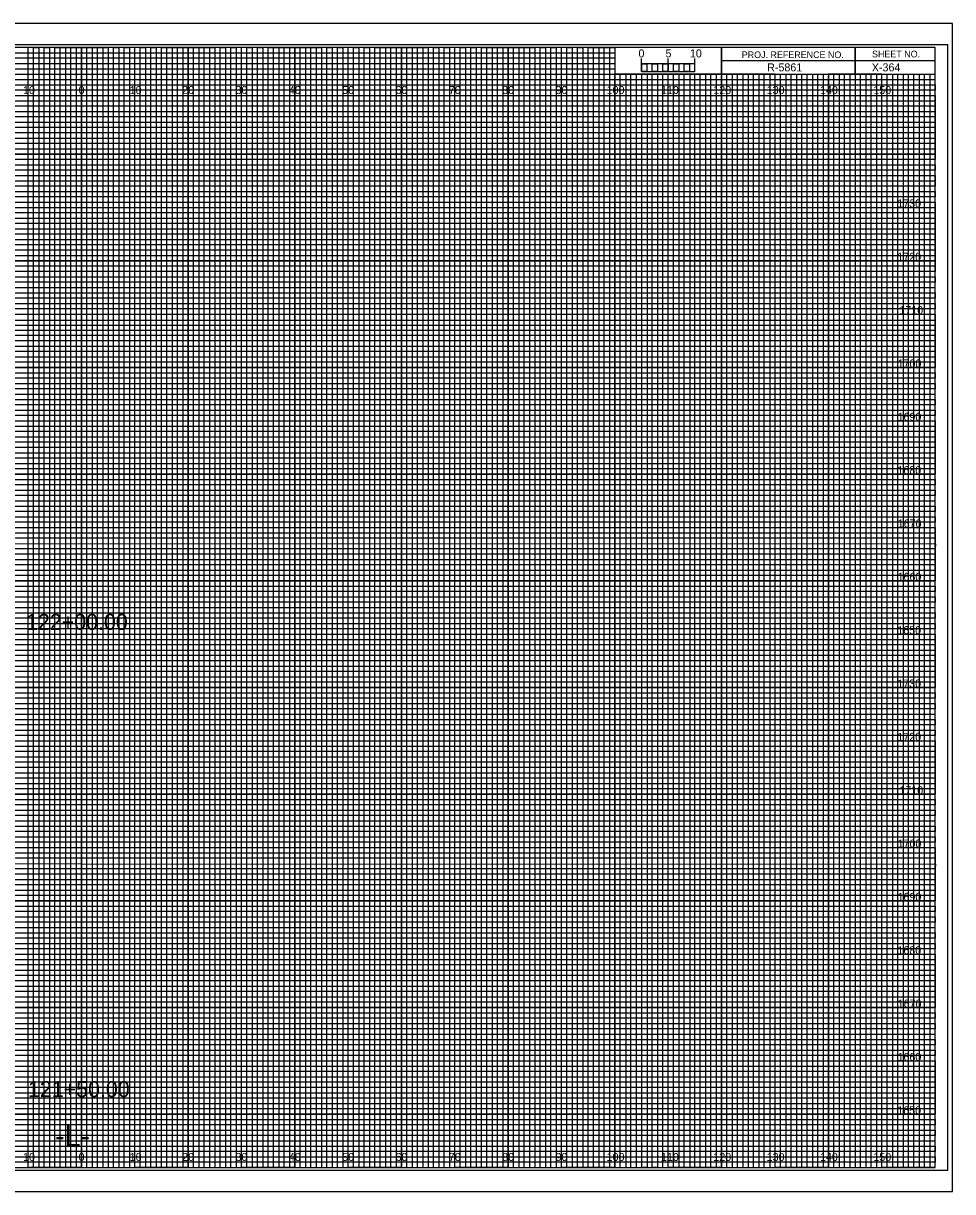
# Model space of a CAD drawing. Extents: x -13 to 323, y -5 to 2414.
# Drawn here: x 149.1 to 323.3, y -4.5 to 214.5 of the extents above; entities that cross this region are included whole.
import ezdxf

# ---------------------------------------------------------------- set-up
doc = ezdxf.new("R2010")
doc.units = 0
for name, color, linetype in [('Prop XS Alignment Label', 7, 'Continuous'), ('Prop XS Bar Scale Labels', 7, 'Continuous'), ('Prop XS Elevation Labels', 7, 'Continuous'), ('Prop XS Offset Labels', 7, 'Continuous'), ('Prop XS Project Number', 7, 'Continuous'), ('Prop XS Sheet Number', 7, 'Continuous'), ('Prop XS Station Labels', 7, 'Continuous'), ('Sheet Cross Section CELL', 7, 'Continuous'), ('Sheet Cross Section Grid Major CELL', 7, 'Continuous'), ('Sheet Cross Section Grid Middle CELL', 7, 'Continuous'), ('Sheet Cross Section Grid Minor 1 CELL', 7, 'Continuous'), ('Sheet Cross Section Grid Minor 2 CELL', 7, 'Continuous'), ('Sheet Cross Section Scale CELL', 7, 'Continuous'), ('Sheet Cutting Line CELL', 7, 'Continuous'), ('Sheet DOT Grid CELL', 7, 'Continuous'), ('Sheet Plot Border Inside CELL', 7, 'Continuous'), ('Sheet Plot Border Outside CELL', 7, 'Continuous')]:
    doc.layers.add(name, color=color, linetype=linetype)

msp = doc.modelspace()

# ---------------------------------------------------------------- linework, layer by layer
at = {"layer": 'Sheet Cross Section CELL'}
for p, q in [((305, 210), (305, 205)), ((305, 205), (305, 210)), ((280, 207.5), (280, 205)), ((320, 207.49), (280, 207.49)), ((280, 205), (320, 205))]:
    msp.add_line(p, q, dxfattribs=at)
for points in [[(320, 210), (0, 210), (0, 0), (320, 0)], [(280, 210), (260, 210), (260, 205.03), (280, 205.03)], [(320, 210), (280, 210), (280, 205), (320, 205)]]:
    msp.add_lwpolyline(points, close=True, dxfattribs=at)
at = {"layer": 'Sheet Cross Section Grid Major CELL'}
for p, q in [((150, 210), (140, 210)), ((150, 0), (150, 210)), ((170, 210), (160, 210)), ((160, 210), (160, 0)), ((170, 0), (170, 210)), ((190, 210), (180, 210)), ((180, 210), (180, 0)), ((190, 0), (190, 210)), ((210, 210), (200, 210)), ((200, 210), (200, 0)), ((210, 0), (210, 210)), ((230, 210), (220, 210)), ((220, 210), (220, 0)), ((230, 0), (230, 210)), ((250, 210), (240, 210)), ((240, 210), (240, 0)), ((250, 0), (250, 210)), ((260, 210), (260, 0)), ((270, 0), (270, 205)), ((290, 205), (280, 205)), ((280, 205), (280, 0)), ((290, 0), (290, 205)), ((310, 205), (300, 205)), ((300, 205), (300, 0)), ((310, 0), (310, 205)), ((160, 0), (150, 0)), ((180, 0), (170, 0)), ((200, 0), (190, 0)), ((220, 0), (210, 0)), ((240, 0), (230, 0)), ((260, 0), (250, 0)), ((280, 0), (270, 0)), ((300, 0), (290, 0)), ((320, 0), (310, 0)), ((320, 0), (320, 0))]:
    msp.add_line(p, q, dxfattribs=at)
for points in [[(0, 200), (320, 200), (320, 190), (0, 190)], [(0, 180), (320, 180), (320, 170), (0, 170)], [(0, 160), (320, 160), (320, 150), (0, 150)], [(0, 140), (320, 140), (320, 130), (0, 130)], [(0, 120), (320, 120), (320, 110), (0, 110)], [(0, 100), (320, 100), (320, 90), (0, 90)], [(0, 80), (320, 80), (320, 70), (0, 70)], [(0, 60), (320, 60), (320, 50), (0, 50)], [(0, 40), (320, 40), (320, 30), (0, 30)], [(0, 20), (320, 20), (320, 10), (0, 10)]]:
    msp.add_lwpolyline(points, dxfattribs=at)
at = {"layer": 'Sheet Cross Section Grid Middle CELL'}
for points in [[(145, 0), (155, 0), (155, 210), (165, 210), (165, 0), (175, 0), (175, 210), (185, 210), (185, 0), (195, 0), (195, 210), (205, 210), (205, 0), (215, 0), (215, 210), (225, 210), (225, 0), (235, 0), (235, 210), (245, 210), (245, 0), (255, 0), (255, 210), (259.93, 210), (260, 210), (260, 205), (264.99, 205), (264.99, 0), (275, 0), (275, 205), (285, 205), (285, 0), (295, 0), (295, 205), (305, 205), (305, 0), (315, 0), (315, 205)], [(0, 205), (275, 205)], [(0, 185), (320, 185), (320, 195), (0, 195)], [(0, 165), (320, 165), (320, 175), (0, 175)], [(0, 145), (320, 145), (320, 155), (0, 155)], [(0, 125), (320, 125), (320, 135), (0, 135)], [(0, 105), (320, 105), (320, 115), (0, 115)], [(0, 85), (320, 85), (320, 95), (0, 95)], [(0, 65), (320, 65), (320, 75), (0, 75)], [(0, 45), (320, 45), (320, 55), (0, 55)], [(0, 25), (320, 25), (320, 35), (0, 35)], [(0, 5), (320, 5), (320, 15), (0, 15)]]:
    msp.add_lwpolyline(points, dxfattribs=at)
at = {"layer": 'Sheet Cross Section Grid Minor 1 CELL'}
for p, q in [((0, 209), (260, 209)), ((260, 209), (260, 207.98)), ((260, 207.98), (0, 207.98)), ((0, 207), (260, 207)), ((260, 205.89), (0, 205.89)), ((260, 207), (260, 205.89)), ((0, 204), (320, 204))]:
    msp.add_line(p, q, dxfattribs=at)
for points in [[(0, 203), (270, 203), (320, 203), (320, 202), (0, 202)], [(0, 201), (320, 201), (320, 199), (0, 199)], [(0, 198), (320, 198), (320, 197), (0, 196.98)], [(0, 196), (320, 196), (320, 194), (0, 194)], [(0, 193), (320, 193), (320, 192), (0, 192)], [(0, 191), (320, 191), (320, 189), (0, 189)], [(0, 188), (320, 188), (320, 187), (0, 187)], [(0, 186), (320, 186), (320, 184), (0, 184)], [(0, 183), (320, 183), (320, 182), (0, 182)], [(0, 181), (320, 181), (320, 179), (0, 179)], [(0, 178), (320, 178), (320, 177), (0, 177)], [(0, 176), (320, 176), (320, 173.95), (320, 173), (320, 172), (0, 172)], [(0, 174), (320, 174), (320, 173), (0, 173)], [(0, 171), (320, 171), (320, 169), (0, 169.03)], [(0, 169.03), (320, 169), (320, 168), (0, 168)], [(0, 167), (320, 167), (320, 166), (0, 166)], [(0, 164), (320, 164), (320, 163), (0, 163)], [(0, 162), (320, 162), (320, 161), (0, 161)], [(-0.07, 158.89), (320, 158.89), (320, 157.88), (-0.07, 157.88)], [(0, 157), (320, 157), (320, 156), (0, 156)], [(0, 154), (320, 154), (320, 153), (0, 153)], [(0, 152), (320, 152), (320, 151), (0, 151)], [(0, 149), (320, 149), (320, 148), (0, 148)], [(0, 147), (320, 147), (320, 146), (0, 146)], [(0, 144), (320, 144), (320, 143), (0, 143)], [(0, 142), (320, 142), (320, 141), (0, 141)], [(0, 139), (320, 139), (319.99, 137.98), (0, 138)], [(0, 137), (320, 137), (320, 136), (0, 136)], [(0, 134), (320, 134), (320, 133), (0, 133)], [(0, 132), (320, 132), (320, 131), (0, 131)], [(0, 129), (320, 129), (320, 128), (0, 128)], [(0, 127), (320, 127), (320, 126), (0, 126)], [(0, 124), (320, 124), (320, 123), (0, 123)], [(0, 122), (320, 122), (320, 121), (0, 121)], [(0, 119), (320, 119), (320, 118), (0, 118)], [(0, 116.99), (320.07, 116.91), (320, 116), (0, 116)], [(0, 114), (320, 114), (320, 113), (0, 113)], [(0, 112), (320, 112), (320, 111), (0, 111)], [(0, 109), (320, 109), (320, 108), (0, 108)], [(0, 107), (320, 107), (320, 106), (0, 106)], [(0, 104), (320, 104), (320, 103), (0, 103)], [(0, 102), (320, 102), (320, 101), (0, 101)], [(0, 99), (320, 99), (320, 98), (0, 98)], [(0, 97), (320, 97), (320, 96), (0, 96)], [(0, 94), (320, 94), (320, 93), (0, 93)], [(0, 92), (320, 92), (320, 91), (0, 91)], [(0, 89), (320, 89), (320, 88), (0, 88)], [(0, 87), (320, 87), (320, 86), (0, 86)], [(0, 84), (320, 84), (320, 83), (0, 83)], [(0, 82), (320, 82), (320, 81), (0, 81)], [(0, 79), (320, 79), (319.99, 77.98), (0, 78)], [(0, 77), (320, 77), (320, 76), (0, 76)], [(0, 74), (320, 74), (320, 73), (0, 73)], [(0, 72), (320, 72), (320, 71), (0, 71)], [(0, 69), (320, 69), (320, 68), (0, 68)], [(0, 67), (320, 67), (320, 66), (0, 66)], [(0, 64), (320, 64), (320, 63), (0, 63)], [(0, 62), (320, 62), (320, 61), (0, 61)], [(0, 59), (320, 59), (320, 58), (0, 58)], [(0, 56.99), (320.07, 56.91), (320, 56), (0, 56)], [(0, 54), (320, 54), (320, 53), (0, 53)], [(0, 52), (320, 52), (320, 51), (0, 51)], [(0, 49), (320, 49), (320, 48), (0, 48)], [(0, 47), (320, 47), (320, 46), (0, 46)], [(0, 44), (320, 44), (320, 43), (0, 43)], [(0, 42), (320, 42), (320, 41), (0, 41)], [(0, 39), (320, 39), (320, 38), (0, 38)], [(0, 37), (320, 37), (320, 36), (0, 36)], [(0, 34), (320, 34), (320, 33), (0, 33)], [(0, 32), (320, 32), (320, 31), (0, 31)], [(0, 29), (320, 29), (320, 28), (0, 28)], [(0, 27), (320, 27), (320, 26), (0, 26)], [(0, 24), (320, 24), (320, 23), (0, 23)], [(0, 22), (320, 22), (320, 21), (0, 21)], [(0, 19), (320, 19), (320, 18), (0, 18)], [(0, 17), (320, 17), (320, 16), (0, 16)], [(0, 14), (320, 14), (320, 13), (0, 13)], [(0, 12), (320, 12), (320, 11), (0, 11)], [(0, 9), (320, 9), (320, 8), (0, 8)], [(0, 7), (320, 7), (320, 6), (0, 6)], [(0, 4), (320, 4), (320, 3), (0, 3)], [(0, 2), (320, 2), (320, 1), (0, 1)]]:
    msp.add_lwpolyline(points, dxfattribs=at)
at = {"layer": 'Sheet Cross Section Grid Minor 2 CELL'}
for p, q in [((267, 205), (266.01, 205)), ((266.01, 205), (266.01, 0)), ((267, 0), (267, 205)), ((269, 205), (268, 205)), ((268, 205), (268, 0)), ((269, 0), (269, 205)), ((266.01, 0), (265, 0)), ((268, 0), (267, 0))]:
    msp.add_line(p, q, dxfattribs=at)
for points in [[(150, 0), (151, 0), (151, 210), (152, 210), (152, 0)], [(152, 0), (153, 0), (153, 210), (154, 210), (154, 0)], [(155, 0), (156, 0), (156, 210), (157, 210), (157, 0)], [(157, 0), (158, 0), (158, 210), (159, 210), (159, 0)], [(160, 0), (161, 0), (161, 210), (162, 210), (162, 0)], [(162, 0), (163, 0), (163, 210), (164, 210), (164, 0)], [(165, 0), (166, 0), (166, 210), (167, 210), (167, 0)], [(167, 0), (168, 0), (168, 210), (169, 210), (169, 0)], [(170, 0), (171, 0), (171, 210), (172, 210), (172, 0)], [(172, 0), (173, 0), (173, 210), (174, 210), (174, 0)], [(175, 0), (176, 0), (176, 210), (177, 210), (177, 0)], [(177, 0), (178, 0), (178, 210), (179, 210), (179, 0)], [(180, 0), (181, 0), (181, 210), (182, 210), (182, 0)], [(182, 0), (183, 0), (183, 210), (184, 210), (184, 0)], [(185, 0), (186, 0), (186, 210), (187, 210), (187, 0)], [(187, 0), (188, 0), (188, 210), (189, 210), (189, 0)], [(190, 0), (191, 0), (191, 210), (192, 210), (192, 0)], [(192, 0), (193, 0), (193, 210), (194, 210), (194, 0)], [(195, 0), (196, 0), (196, 210), (197, 210), (197, 0)], [(197, 0), (198, 0), (198, 210), (199, 210), (199, 0)], [(200, 0), (201, 0), (201, 210), (202, 210), (202, 0)], [(202, 0), (203, 0), (203, 210), (204, 210), (204, 0)], [(205, 0), (206, 0), (206, 210), (207, 210), (207, 0)], [(207, 0), (208, 0), (208, 210), (209, 210), (209, 0)], [(210, 0), (211, 0), (211, 210), (212, 210), (212, 0)], [(212, 0), (213, 0), (213, 210), (214, 210), (214, 0)], [(215, 0), (216, 0), (216, 210), (217, 210), (217, 0)], [(217, 0), (218, 0), (218, 210), (219, 210), (219, 0)], [(220, 0), (221, 0), (221, 210), (222, 210), (222, 0)], [(222, 0), (223, 0), (223, 210), (224, 210), (224, 0)], [(225, 0), (226, 0), (226, 210), (227, 210), (227, 0)], [(227, 0), (228, 0), (228, 210), (229, 210), (229, 0)], [(230, 0), (231, 0), (231, 210), (232, 210), (232, 0)], [(232, 0), (233, 0), (233, 210), (234, 210), (234, 0)], [(235, 0), (236, 0), (236, 210), (237, 210), (237, 0)], [(237, 0), (238, 0), (238, 210), (239, 210), (239, 0)], [(240, 0), (241, 0), (241, 210), (242, 210), (242, 0)], [(242, 0), (243, 0), (243, 210), (244, 210), (244, 0)], [(245, 0), (246, 0), (246, 210), (247, 210), (247, 0)], [(247, 0), (248, 0), (248, 210), (249, 210), (249, 0)], [(250, 0), (251, 0), (251, 210), (252, 210), (252, 0)], [(252, 0), (253, 0), (253, 210), (254, 210), (254, 0)], [(255, 0), (256, 0), (256, 210), (257, 210), (257, 0)], [(257, 0), (258, 0), (258, 210), (259, 210), (259, 0)], [(260, 0), (261, 0), (261, 205), (262.02, 205), (262.02, 0)], [(262, 0), (263, 0), (263, 205), (263.99, 205), (263.99, 0)], [(270, 0), (270.98, 0), (270.98, 205), (272, 205), (272, 0)], [(272, 0), (273, 0), (273, 205), (274.05, 205), (274.05, 0)], [(275, 0), (276, 0), (276, 205), (277, 205), (277, 0)], [(277, 0), (278, 0), (278, 205), (279, 205), (279, 0)], [(280, 0), (281, 0), (281, 205), (282, 205), (282, 0)], [(282, 0), (283, 0), (283, 205), (284, 205), (284, 0)], [(285, 0), (286, 0), (286, 205), (287, 205), (287, 0)], [(287, 0), (288, 0), (288, 205), (289, 205), (289, 0)], [(290, 0), (291, 0), (291, 205), (292, 205), (292, 0)], [(292, 0), (293, 0), (293, 205), (294, 205), (294, 0)], [(295, 0), (296, 0), (296, 205), (297, 205), (297, 0)], [(297, 0), (298, 0), (298, 205), (299, 205), (299, 0)], [(300, 0), (301, 0), (301, 205), (302, 205), (302, 0)], [(302, 0), (303, 0), (303, 205), (304, 205), (304, 0)], [(305, 0), (306, 0), (306, 205), (307, 205), (307, 0)], [(307, 0), (308, 0), (308, 205), (309, 205), (309, 0)], [(310, 0), (311, 0), (311, 205), (312, 205), (312, 0)], [(312, 0), (313, 0), (313, 205), (314, 205), (314, 0)], [(315, 0), (316, 0), (316, 205), (317, 205), (317, 0)], [(317, 0), (318, 0), (318, 205), (319, 205), (319, 0)]]:
    msp.add_lwpolyline(points, dxfattribs=at)
at = {"layer": 'Sheet Cross Section Scale CELL'}
for p, q in [((265, 205.49), (265, 207.9)), ((265, 206.9), (265, 207.9)), ((270, 205.49), (270, 207.9)), ((275, 205.49), (275, 207.9)), ((275, 206.9), (275, 207.9))]:
    msp.add_line(p, q, dxfattribs=at)
for points in [[(275, 206.9), (265, 206.9), (265, 205.49), (275, 205.49)], [(265, 206.9), (266, 206.9), (266, 205.49), (265, 205.49)], [(267, 206.9), (268, 206.9), (268, 205.49), (267, 205.49)], [(269, 206.9), (270, 206.9), (270, 205.49), (269, 205.49)], [(271, 206.9), (272, 206.9), (272, 205.49), (271, 205.49)], [(273, 206.9), (274, 206.9), (274, 205.49), (273, 205.49)]]:
    msp.add_lwpolyline(points, close=True, dxfattribs=at)
at = {"layer": 'Sheet Cutting Line CELL'}
for p, q in [((323.3, 214.5), (-13.4, 214.5)), ((-13.4, -4.5), (323.3, -4.5))]:
    msp.add_line(p, q, dxfattribs=at)
at = {"layer": 'Sheet DOT Grid CELL'}
for p, q in [((150, 0), (150, 210)), ((160, 0), (160, 210)), ((170, 0), (170, 210)), ((180, 0), (180, 210)), ((190, 0), (190, 210)), ((200, 0), (200, 210)), ((210, 0), (210, 210)), ((220, 0), (220, 210)), ((230, 0), (230, 210)), ((240, 0), (240, 210)), ((250, 0), (250, 210)), ((260, 0), (260, 204.69)), ((270, 0), (270, 204.69)), ((280, 0), (280, 204.69)), ((290, 0), (290, 204.69)), ((300, 0), (300, 204.69)), ((310, 0), (310, 204.69)), ((0, 200), (320, 200)), ((0, 190), (320, 190)), ((0, 180), (320, 180)), ((0, 170), (320, 170)), ((0, 160), (320, 160)), ((0, 150), (320, 150)), ((0, 140), (320, 140)), ((0, 130), (320, 130)), ((0, 120), (320, 120)), ((0, 110), (320, 110)), ((0, 100), (320, 100)), ((0, 90), (320, 90)), ((0, 80), (320, 80)), ((0, 70), (320, 70)), ((0, 60), (320, 60)), ((0, 50), (320, 50)), ((0, 40), (320, 40)), ((0, 30), (320, 30)), ((0, 20), (320, 20)), ((0, 10), (320, 10))]:
    msp.add_line(p, q, dxfattribs=at)
at = {"layer": 'Sheet Plot Border Inside CELL'}
msp.add_lwpolyline([(-10.8, -0.5), (322.4, -0.5), (322.4, 210.5), (-10.8, 210.5)], close=True, dxfattribs=at)
at = {"layer": 'Sheet Plot Border Outside CELL'}
msp.add_lwpolyline([(-13.4, -4.5), (323.3, -4.5), (323.3, 214.5), (-13.4, 214.5)], close=True, dxfattribs=at)

# ---------------------------------------------------------------- texts
at = {"layer": 'Prop XS Alignment Label'}
msp.add_text('-L-', height=4, dxfattribs=at).set_placement((155.06, 4))
at = {"layer": 'Prop XS Bar Scale Labels'}
for s, p in [('5', (269.47, 208.12)), ('10', (274.04, 208.12))]:
    msp.add_text(s, height=1.5, dxfattribs=at).set_placement(p)
at = {"layer": 'Prop XS Elevation Labels'}
for s, p in [('1730', (312.92, 180)), ('1720', (312.93, 170)), ('1710', (313.31, 160)), ('1700', (312.98, 150)), ('1690', (312.97, 140)), ('1680', (312.95, 130)), ('1670', (313, 120)), ('1660', (312.97, 110)), ('1650', (312.92, 100)), ('1730', (312.92, 90)), ('1720', (312.93, 80)), ('1710', (313.31, 70)), ('1700', (312.98, 60)), ('1690', (312.97, 50)), ('1680', (312.95, 40)), ('1670', (313, 30)), ('1660', (312.97, 20)), ('1650', (312.92, 10))]:
    msp.add_text(s, height=1.5, dxfattribs=at).set_placement(p)
at = {"layer": 'Prop XS Offset Labels'}
for s, p in [('10', (149.04, 201.25)), ('0', (159.45, 201.25)), ('0', (159.45, 201.25)), ('10', (169.04, 201.25)), ('20', (178.86, 201.25)), ('30', (188.86, 201.25)), ('40', (198.86, 201.25)), ('50', (208.86, 201.25)), ('60', (218.86, 201.25)), ('70', (228.86, 201.25)), ('80', (238.86, 201.25)), ('90', (248.86, 201.25)), ('100', (258.44, 201.25)), ('110', (268.62, 201.25)), ('120', (278.44, 201.25)), ('130', (288.44, 201.25)), ('140', (298.44, 201.25)), ('150', (308.44, 201.25)), ('10', (149.04, 1.25)), ('0', (159.45, 1.25)), ('0', (159.45, 1.25)), ('10', (169.04, 1.25)), ('20', (178.86, 1.25)), ('30', (188.86, 1.25)), ('40', (198.86, 1.25)), ('50', (208.86, 1.25)), ('60', (218.86, 1.25)), ('70', (228.86, 1.25)), ('80', (238.86, 1.25)), ('90', (248.86, 1.25)), ('100', (258.44, 1.25)), ('110', (268.62, 1.25)), ('120', (278.44, 1.25)), ('130', (288.44, 1.25)), ('140', (298.44, 1.25)), ('150', (308.44, 1.25))]:
    msp.add_text(s, height=1.5, dxfattribs=at).set_placement(p)
at = {"layer": 'Prop XS Project Number'}
msp.add_text('R-5861', height=1.5, dxfattribs=at).set_placement((288.53, 205.5))
at = {"layer": 'Prop XS Sheet Number'}
msp.add_text('X-364', height=1.5, dxfattribs=at).set_placement((308.15, 205.5))
at = {"layer": 'Prop XS Station Labels'}
for s, p in [('122+00.00', (149.59, 100.8)), ('121+50.00', (149.95, 13.21))]:
    msp.add_text(s, height=3, dxfattribs=at).set_placement(p)
at = {"layer": 'Sheet Cross Section CELL'}
for s, p in [('PROJ. REFERENCE NO.', (283.77, 207.99)), ('SHEET NO.', (308.19, 208.12))]:
    msp.add_text(s, height=1.25, dxfattribs=at).set_placement(p)
at = {"layer": 'Sheet Cross Section Scale CELL'}
msp.add_text('0', height=1.5, dxfattribs=at).set_placement((264.41, 208.12))

doc.saveas('drawing.dxf')
